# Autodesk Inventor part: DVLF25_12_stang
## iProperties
Created: 2010-03
Part Number: DVLF25_12_stang
Document SubType Name: Modeling
Designer: TB
Mass: 30.5021 g
Surface Area: 88.4185 cm^2
Volume: 30.5021 cm^3
Density: 1 g/cm^3
Author: TB
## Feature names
1. Revolution1
2. Fillet1
3. Revolution2
